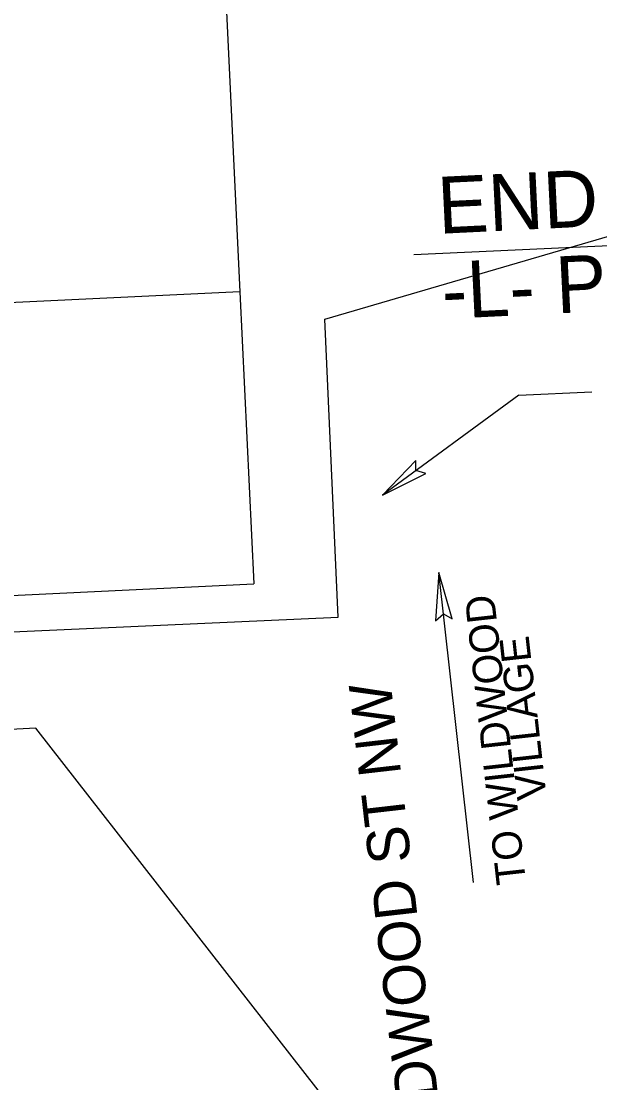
# Model space of a CAD drawing. Extents: x 2170913 to 2188101, y 74009 to 87693.
# Drawn here: x 2175486 to 2176242, y 78074 to 79461 of the extents above; entities that cross this region are included whole.
import ezdxf

# ---------------------------------------------------------------- set-up
doc = ezdxf.new("R2010")
doc.units = 0
for name, color, linetype in [('CTL Primary Horizontal and Vertical Cogo Elevation', 7, 'Continuous'), ('Exist Property Iron Pin CELL', 7, 'Continuous'), ('Exist Property Iron Pin Cogo Number', 7, 'Continuous'), ('Exist Structure Minor Pipes HDPE 30 Inch', 7, 'Continuous')]:
    doc.layers.add(name, color=color, linetype=linetype)

msp = doc.modelspace()

# ---------------------------------------------------------------- linework, layer by layer
at = {"layer": 'CTL Primary Horizontal and Vertical Cogo Elevation'}
for p, q in [((2175771.5, 79107.1), (2175789.7, 78725.5)), ((2176136.1, 78971.9), (2175958.1, 78841.2)), ((2176136.1, 78971.9), (2176231.6, 78976.4)), ((2172841.7, 78585.3), (2175789.7, 78725.5))]:
    msp.add_line(p, q, dxfattribs=at)
msp.add_lwpolyline([(2172704.4, 81472.7), (2175652.3, 81612.9), (2175771.5, 79107.1), (2172823.6, 78966.9)], close=True, dxfattribs=at)
at = {"layer": 'Exist Property Iron Pin CELL'}
for p, q in [((2177462.8, 79224.8), (2175998.9, 79155.2)), ((2176077, 78335.4), (2176031.8, 78740.2)), ((2175504.9, 78536.7), (2174320.5, 78480.3)), ((2176155.5, 77703.4), (2175504.9, 78536.7))]:
    msp.add_line(p, q, dxfattribs=at)
at = {"layer": 'Exist Property Iron Pin Cogo Number'}
for points in [[(2176001.4, 78886.7), (2175958.1, 78841.2), (2176014.6, 78869.6), (2176001.7, 78873.7)], [(2176048.9, 78679.7), (2176031.8, 78740.2), (2176027.4, 78677.1), (2176037.5, 78686.1)]]:
    msp.add_lwpolyline(points, close=True, dxfattribs=at)
at = {"layer": 'Exist Structure Minor Pipes HDPE 30 Inch'}
msp.add_lwpolyline([(2174631.9, 78625), (2175899.9, 78682), (2175882.4, 79071.3), (2176656, 79297.5), (2177391.1, 79031.4), (2178152.3, 78655.2), (2178303.3, 76031.7), (2174802.3, 75830.2), (2174781.3, 76195.1), (2174799.2, 76231.4), (2174723.3, 76523.2)], close=True, dxfattribs=at)

# ---------------------------------------------------------------- texts
at = {"layer": 'Exist Property Iron Pin CELL'}
for s, height, rotation, p in [('END TIP PROJECT R-5857', 74.313, 2.8013, (2176031.7, 79182.8)), ('-L- POT STA 54+25.00', 74.313, 2.8013, (2176037.1, 79071.5)), ('TO WILDWOOD', 38.533, 96.3514, (2176145.6, 78334.6)), ('VILLAGE', 38.53, 96.3514, (2176172.6, 78445.3)), ('WILDWOOD ST NW', 55.047, 96.5388, (2176045.8, 77924.3))]:
    msp.add_text(s, height=height, rotation=rotation, dxfattribs=at).set_placement(p)

doc.saveas('drawing.dxf')
